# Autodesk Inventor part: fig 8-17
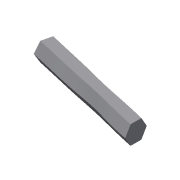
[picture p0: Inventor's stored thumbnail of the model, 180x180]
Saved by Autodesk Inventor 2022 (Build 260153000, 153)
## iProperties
Created: 2004-05
Part Number: fig 8-17
Document SubType Name: Modeling
Designer: CADCIM Technologies
Manufacturer: Standard
Standards Organization: Custom
Density: 1 g/cm^3
Material: Generic
Appearance: Default
Author: CADCIM Technologies
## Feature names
1. Sweep7
## Parameters: d6 = 0, d7 = 0
